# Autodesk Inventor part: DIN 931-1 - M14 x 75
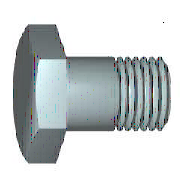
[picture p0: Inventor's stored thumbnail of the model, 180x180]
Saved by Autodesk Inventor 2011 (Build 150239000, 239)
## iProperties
Created: 2010-02
Part Number: DIN 931-1 - M14 x 75
Material: Steel, Mild
Description: Hex-Head Bolt
Document SubType Name: Modeling
Standard: DIN 931-1
Designer: PC
Standard Revision: 2001
Standards Organization: DIN
Language: en-US
Size Designation: M14 x 75
Categories: <MemberInstance><Categories><Category DisplayName="Fasteners" InternalName="e4da775c-781d-43d5-af7c-5136215cf5a6" Mnemonic="FSTN"><Category DisplayName="Bolts"
Density: 1 g/cm^3
IsCustomPart: 0
Author: PC
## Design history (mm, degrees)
body "Solid1"
workplane "Work Plane1"
revolve "Body" stored, may be unused: angle "d12" = 90 deg
sketch "Sketch2"
  geometry: L1 (0, 12.702)-(11, 6.351); L2 (11, 6.351)-(11, -6.351); L3 (11, -6.351)-(0, -12.702); L4 (0, -12.702)-(-11, -6.351); L5 (-11, -6.351)-(-11, 6.351); L6 (-11, 6.351)-(0, 12.702); 2 further points
  constraints: 12 end point, 1 coincident, 1 vertical, 11 other
  dimensions: "d11" = 22 distance between parallel lines of L5 L2 (= SW)
extrude "Head" join sketch "Sketch2" distance "d3" = 8.2 (= KOH - SD); taper "d4" = 0 deg
revolve "Chamfer1" stored, may be unused: angle "d21" = 90 deg
feature "Thread" dims "d15" = 34 (= GEL), "d16" = 0
chamfer "Chamfer2" distance "d6" = 1.2269 (= -0.5 x SPD + 0.5 x GD); stored, may be unused: second distance "d7" = 1.227 (computed from GUL), angle "d55" = 45 deg
sketch "Sketch1"
  geometry: L1 (0, 10.25)-(0, 7); L2 (41, 7)-(75, 7); L3 (75, 7)-(75, 0); L4 (75, 0)-(-0.6, 0); L5 (-15.72, 0)-(90.12, 0) reference; L6 (-0.6, 0)-(-0.6, 10.25); L7 (-0.6, 10.25)-(0, 10.25); L8 (41, 7)-(39.773, 7); L9 (39.773, 7)-(0, 7); L10 (0, -2.05)-(0, 12.3) reference
  constraints: 16 end point, 2 collinear, 2 perpendicular, 1 parallel
  dimensions: "d0" = 75 distance between parallel lines of L3 L1 (= NLG); "d1" = 34 distance from line of L2.start L3 (= GEL); "d2" = 14 diameter of L2 L4 (= GD); "d9" = 0.6001 distance between parallel lines of L6 L1 (computed from SD); "d10" = 20.5 diameter of L7 L4 (= SD2); "d13" = 1.227 distance of L2.start L8.end (computed from GAL); "d14" = 14 diameter of L9 L4 (= BDM)
sketch "Sketch4"
  geometry: L1 (-8.8, 11)-(-8.8, 12.702); L2 (-8.8, 12.702)-(-7.818, 12.702); L3 (-7.818, 12.702)-(-8.8, 11); L4 (-10.44, 0)-(1.04, 0) reference; L5 (-0.6, 12.702)-(-8.8, 12.702) reference; L6 (-8.8, 6.351)-(-8.8, 12.702) reference
  constraints: 6 end point, 2 collinear, 1 perpendicular, 1 vertical
  dimensions: "d5" = 30 deg angle of L3 L1 (= ANG1); "d19" = 22 diameter of L1.start L4 (= SW0)
other parameters: "NLG" = 75 [user parameter; used in 1 equation term], "GD" = 14 (= NND) [user parameter; used in 2 equation terms], "BDM" = 14 (= NND) [user parameter; used in 1 equation term], "KOH" = 8.8 [user parameter; used in 1 equation term], "GEL" = 34 [user parameter; used in 2 equation terms], "SW" = 22 [user parameter; used in 3 equation terms], "SW0" = 22 (= SW) [user parameter; used in 1 equation term], "SPD" = 11.5462 (= NND - 1.2269 x PTC) [user parameter; used in 1 equation term], "SD2" = 20.5 [user parameter; used in 1 equation term], "SD" = 0.6 [user parameter; used in 2 equation terms], "ANG1" = 30 deg [user parameter; used in 1 equation term], "GAL" = 1.2269 (= 0.61345 x PTC) [user parameter; used in 1 equation term], "GUL" = 1.2269 (= 0.61345 x PTC) [user parameter; used in 1 equation term], "d8" = 0, "RR" = 0.6 [user parameter], "d57" = 0, "d58" = 0, "TPU" = 5 (computed from PTC) [user parameter], "GD1" = 11.5462 (= THREADDIA - 1.2269 x PTC) [user parameter], "THREADDIA" = 14 [user parameter; used in 1 equation term], "TOA" = 30 deg [user parameter], "PTC" = 2 [user parameter; used in 5 equation terms], "NND" = 14 [user parameter; used in 3 equation terms], "E0" = 25.41 (= 1.155 x SW) [user parameter]
